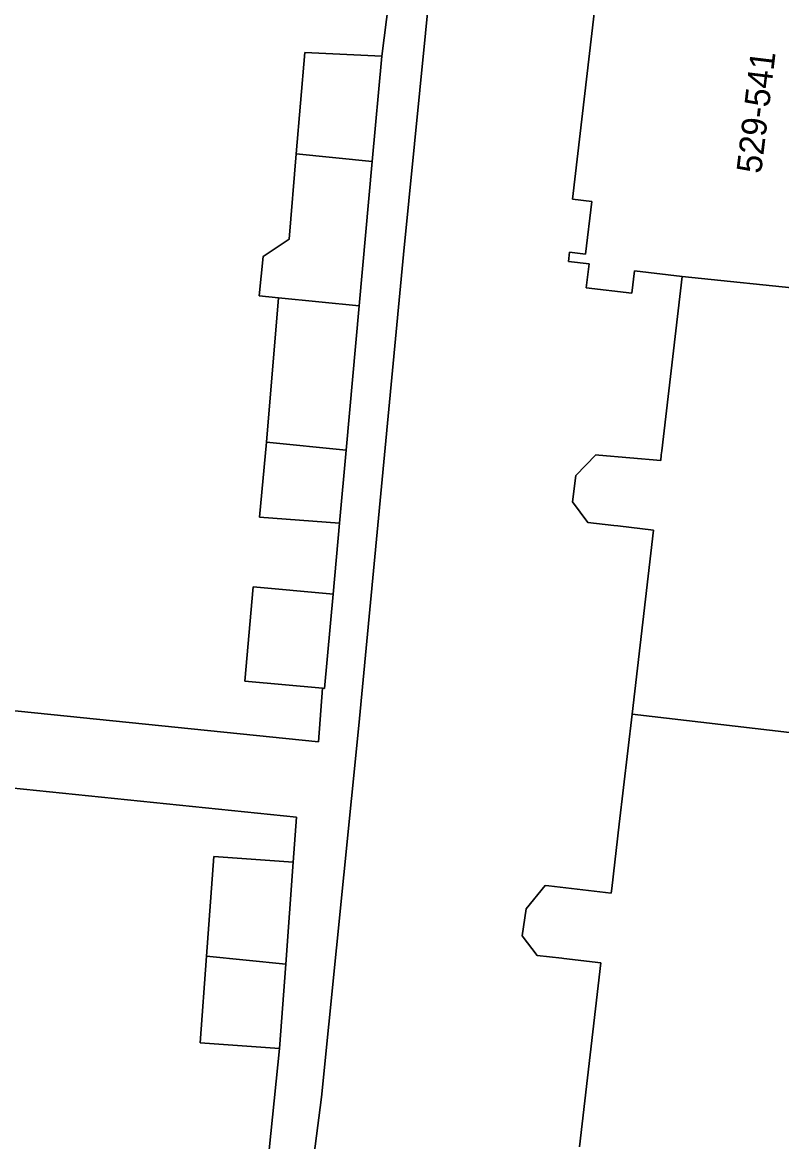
# Model space of a CAD drawing. Extents: x 160856 to 161310, y 384024 to 384878.
# Drawn here: x 161199.07 to 161229.52, y 384514 to 384558.85 of the extents above; entities that cross this region are included whole.
import ezdxf

# ---------------------------------------------------------------- set-up
doc = ezdxf.new("R2010")
doc.units = 0
for name, color, linetype in [('IMGEO_Erf', 7, 'Continuous'), ('IMGEO_Pand', 7, 'Continuous'), ('IMGEO_Pand_nummerreeks', 7, 'Continuous'), ('IMGEO_Voetpad_open', 7, 'Continuous')]:
    doc.layers.add(name, color=color, linetype=linetype)

msp = doc.modelspace()

# ---------------------------------------------------------------- linework, layer by layer
at = {"layer": 'IMGEO_Erf'}
for points in [[(161218.539, 384591.638), (161214.362, 384549.557), (161212.573, 384530.677), (161211.066, 384515.775), (161208.737, 384497.685), (161207.136, 384481.547), (161205.809, 384471.484), (161203.982, 384463.225), (161201.696, 384458.913), (161189.991, 384439.907)], [(161198.712, 384560.579), (161198.122, 384554.802), (161197.533, 384549.025), (161196.944, 384543.248), (161196.355, 384537.47), (161195.754, 384531.575), (161210.945, 384530.022), (161211.113, 384532.169), (161207.991, 384532.451), (161208.332, 384536.226), (161211.409, 384535.947), (161211.532, 384535.936), (161211.789, 384538.778), (161208.586, 384539.029), (161208.858, 384542.031), (161209.342, 384547.819), (161208.572, 384547.898), (161208.732, 384549.47), (161209.771, 384550.16), (161210.057, 384553.584), (161210.396, 384557.64), (161213.484, 384557.505), (161213.957, 384561.189)], [(161221.41, 384513.788), (161222.273, 384521.163), (161220.783, 384521.337), (161220.714, 384521.345), (161219.719, 384521.461), (161219.123, 384522.244), (161219.282, 384523.324), (161220.046, 384524.258), (161220.19, 384524.242), (161222.685, 384523.95), (161222.707, 384524.142), (161223.009, 384526.722), (161223.524, 384531.132), (161224.387, 384538.506), (161222.958, 384538.674), (161222.792, 384538.693), (161221.75, 384538.815), (161221.131, 384539.643), (161221.264, 384540.699), (161222.067, 384541.519), (161222.196, 384541.508), (161224.679, 384541.297), (161224.697, 384541.516), (161224.717, 384541.685), (161225.533, 384548.667), (161223.624, 384548.891), (161223.52, 384548.001), (161221.688, 384548.215), (161221.799, 384549.171), (161220.972, 384549.268), (161221.016, 384549.64), (161221.66, 384549.565), (161221.906, 384551.675), (161221.133, 384551.765), (161222.192, 384560.826)], [(161198.267, 384468.313), (161202.662, 384466.796), (161201.473, 384463.351), (161202.722, 384462.873), (161204.673, 384471.575), (161205.845, 384483.039), (161207.023, 384494.563), (161208.214, 384506.205), (161209.392, 384517.725), (161206.204, 384517.959), (161206.458, 384521.431), (161206.75, 384525.429), (161209.939, 384525.196), (161210.071, 384527.002), (161195.459, 384528.498)]]:
    msp.add_lwpolyline(points, dxfattribs=at)
at = {"layer": 'IMGEO_Pand'}
for points in [[(161222.192, 384560.826), (161221.133, 384551.765), (161221.906, 384551.675), (161221.66, 384549.565), (161221.016, 384549.64), (161220.972, 384549.268), (161221.799, 384549.171), (161221.688, 384548.215), (161223.52, 384548.001), (161223.624, 384548.891), (161225.533, 384548.667), (161230.709, 384548.137), (161232.592, 384564.236)], [(161230.709, 384548.137), (161225.533, 384548.667), (161224.717, 384541.685), (161224.697, 384541.516), (161224.679, 384541.297), (161222.196, 384541.508), (161222.067, 384541.519), (161221.264, 384540.699), (161221.131, 384539.643), (161221.75, 384538.815), (161222.792, 384538.693), (161222.958, 384538.674), (161224.387, 384538.506), (161223.524, 384531.132), (161235.341, 384529.749)], [(161235.341, 384529.749), (161223.524, 384531.132), (161223.009, 384526.722), (161222.707, 384524.142), (161222.685, 384523.95), (161220.19, 384524.242), (161220.046, 384524.258), (161219.282, 384523.324), (161219.123, 384522.244), (161219.719, 384521.461), (161220.714, 384521.345), (161220.783, 384521.337), (161222.273, 384521.163), (161221.41, 384513.788)]]:
    msp.add_lwpolyline(points, dxfattribs=at)
for points in [[(161213.484, 384557.505), (161210.396, 384557.64), (161210.057, 384553.584), (161213.101, 384553.273)], [(161213.101, 384553.273), (161210.057, 384553.584), (161209.771, 384550.16), (161208.732, 384549.47), (161208.572, 384547.898), (161209.342, 384547.819), (161212.578, 384547.49)], [(161212.578, 384547.49), (161209.342, 384547.819), (161208.858, 384542.031), (161212.054, 384541.705)], [(161212.054, 384541.705), (161208.858, 384542.031), (161208.586, 384539.029), (161211.789, 384538.778)], [(161211.409, 384535.947), (161208.332, 384536.226), (161207.991, 384532.451), (161211.113, 384532.169), (161211.19, 384532.162), (161211.532, 384535.936)], [(161209.64, 384521.106), (161209.939, 384525.196), (161206.75, 384525.429), (161206.458, 384521.431)], [(161209.64, 384521.106), (161206.458, 384521.431), (161206.204, 384517.959), (161209.392, 384517.725)]]:
    msp.add_lwpolyline(points, close=True, dxfattribs=at)
at = {"layer": 'IMGEO_Voetpad_open'}
for points in [[(161189.991, 384439.907), (161201.696, 384458.913), (161203.982, 384463.225), (161205.809, 384471.484), (161207.136, 384481.547), (161208.737, 384497.685), (161211.066, 384515.775), (161212.573, 384530.677), (161214.362, 384549.557), (161218.539, 384591.638)], [(161213.957, 384561.189), (161213.484, 384557.505), (161213.101, 384553.273), (161212.578, 384547.49), (161212.054, 384541.705), (161211.789, 384538.778), (161211.532, 384535.936), (161211.19, 384532.162), (161211.113, 384532.169), (161210.945, 384530.022), (161195.754, 384531.575)], [(161195.459, 384528.498), (161210.071, 384527.002), (161209.939, 384525.196), (161209.64, 384521.106), (161209.392, 384517.725), (161208.214, 384506.205), (161207.023, 384494.563), (161205.845, 384483.039), (161204.673, 384471.575), (161202.722, 384462.873), (161201.473, 384463.351), (161197.078, 384464.867)]]:
    msp.add_lwpolyline(points, dxfattribs=at)

# ---------------------------------------------------------------- texts
at = {"layer": 'IMGEO_Pand_nummerreeks'}
msp.add_text('529-541', height=1, rotation=83.1731, dxfattribs=at).set_placement((161228.699, 384552.765))

doc.saveas('drawing.dxf')
